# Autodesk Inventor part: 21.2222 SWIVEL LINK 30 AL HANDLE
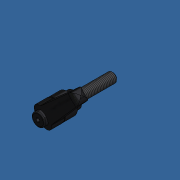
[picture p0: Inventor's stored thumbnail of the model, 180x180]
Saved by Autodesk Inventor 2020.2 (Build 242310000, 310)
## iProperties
Part Number: 21.2222 SWIVEL LINK 30 AL HANDLE
Material: Steel
Document SubType Name: Modeling
Designer: amoles
Appearance: Plate
Mass: 107.098 g
Surface Area: 50.2073 cm^2
Volume: 13.6431 cm^3
Density: 7.85 g/cm^3
Author: amoles
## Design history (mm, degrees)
feature "Base1"
thread "Thread1" dims "d0" = 31.2, "d1" = 0
body "Solid1"
